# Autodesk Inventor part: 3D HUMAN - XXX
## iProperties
Category: PART
Company: Cross Bros.
Shininess: 64.0
Length Units: 11272
Angle Units: 11279
Time Units: 11290
Mass Units: 11286
Length Display Precision: 3
Angle Display Precision: 2
Compacted: True
Part Number: 3D HUMAN - XXX
Document SubType Name: Modeling
Created: 2003-03
Designer: MVF
Catalog Web Link: www.crossbros.com
Density: 0.0
Volumn: 0.0
Area: 0.0
PropertySet Name: Model Information
Control State: 0
Master: False
Checked Out: False
Author: MVF
Title: iMike
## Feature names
1. Extrusion1
2. Extrusion3
3. Mirror1
4. Extrusion4
5. Fillet18
6. Fillet19
7. Fillet20
8. Fillet21
